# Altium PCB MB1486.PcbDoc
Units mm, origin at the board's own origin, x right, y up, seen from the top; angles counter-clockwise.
Board outline 25 x 31.2 mm, 4 copper layers (Top Layer, Signal Layer 1, Signal Layer 2, Bottom Layer), stack 1.2 mm thick; 31 components, 28 nets, 234 pads, 74 vias.
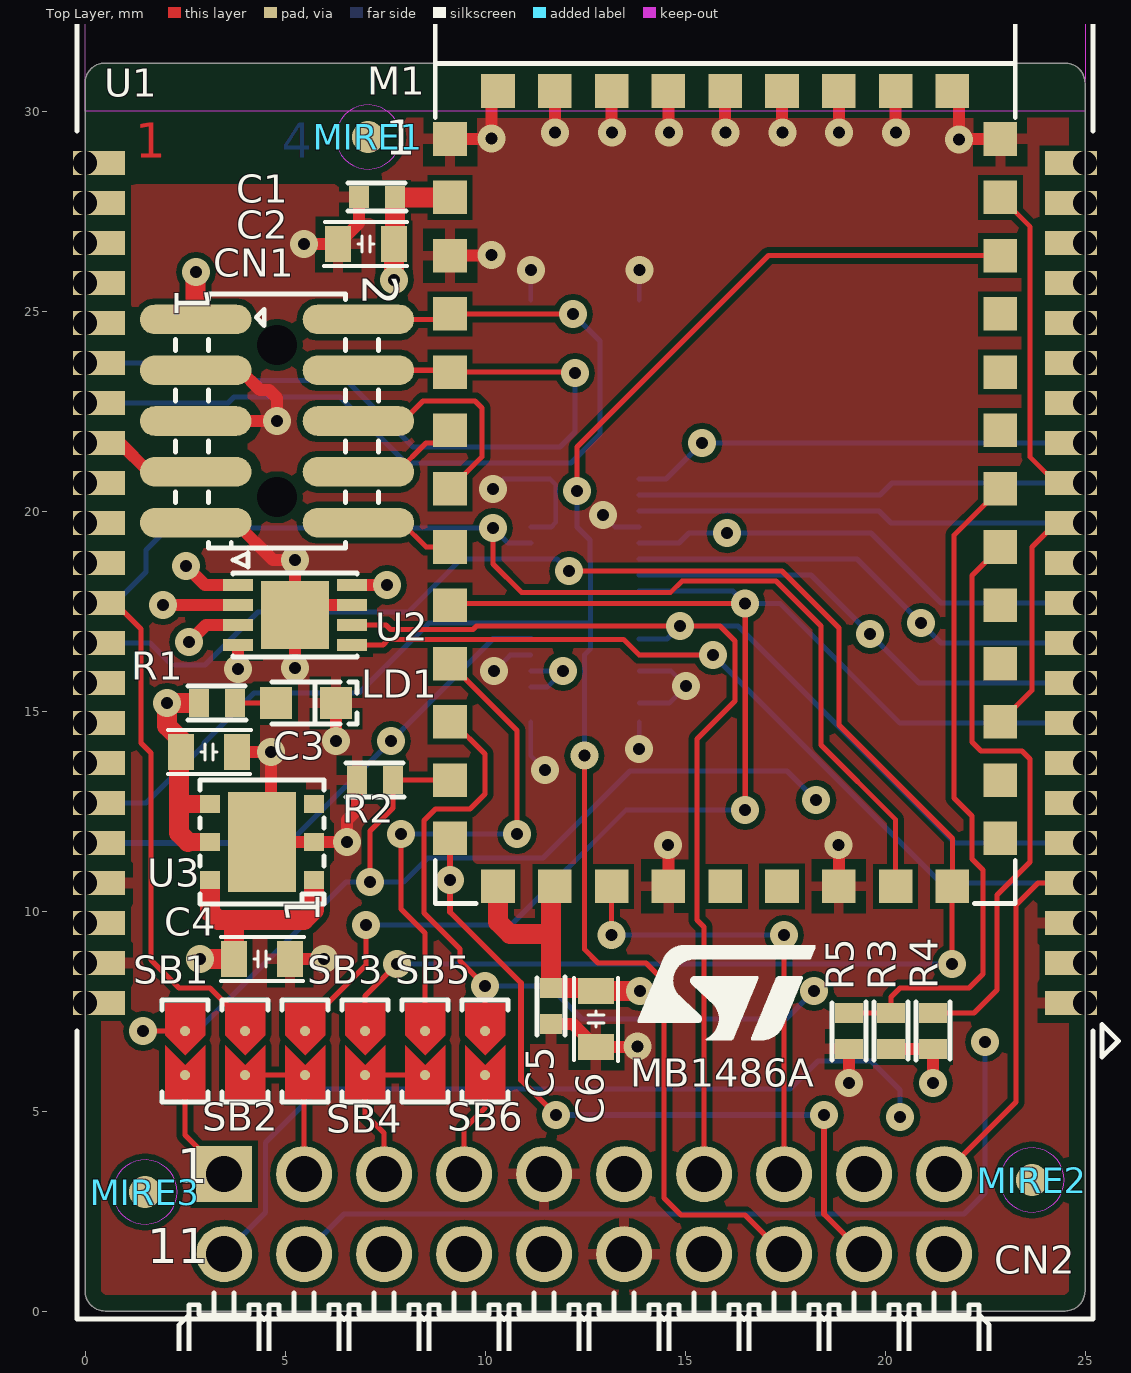
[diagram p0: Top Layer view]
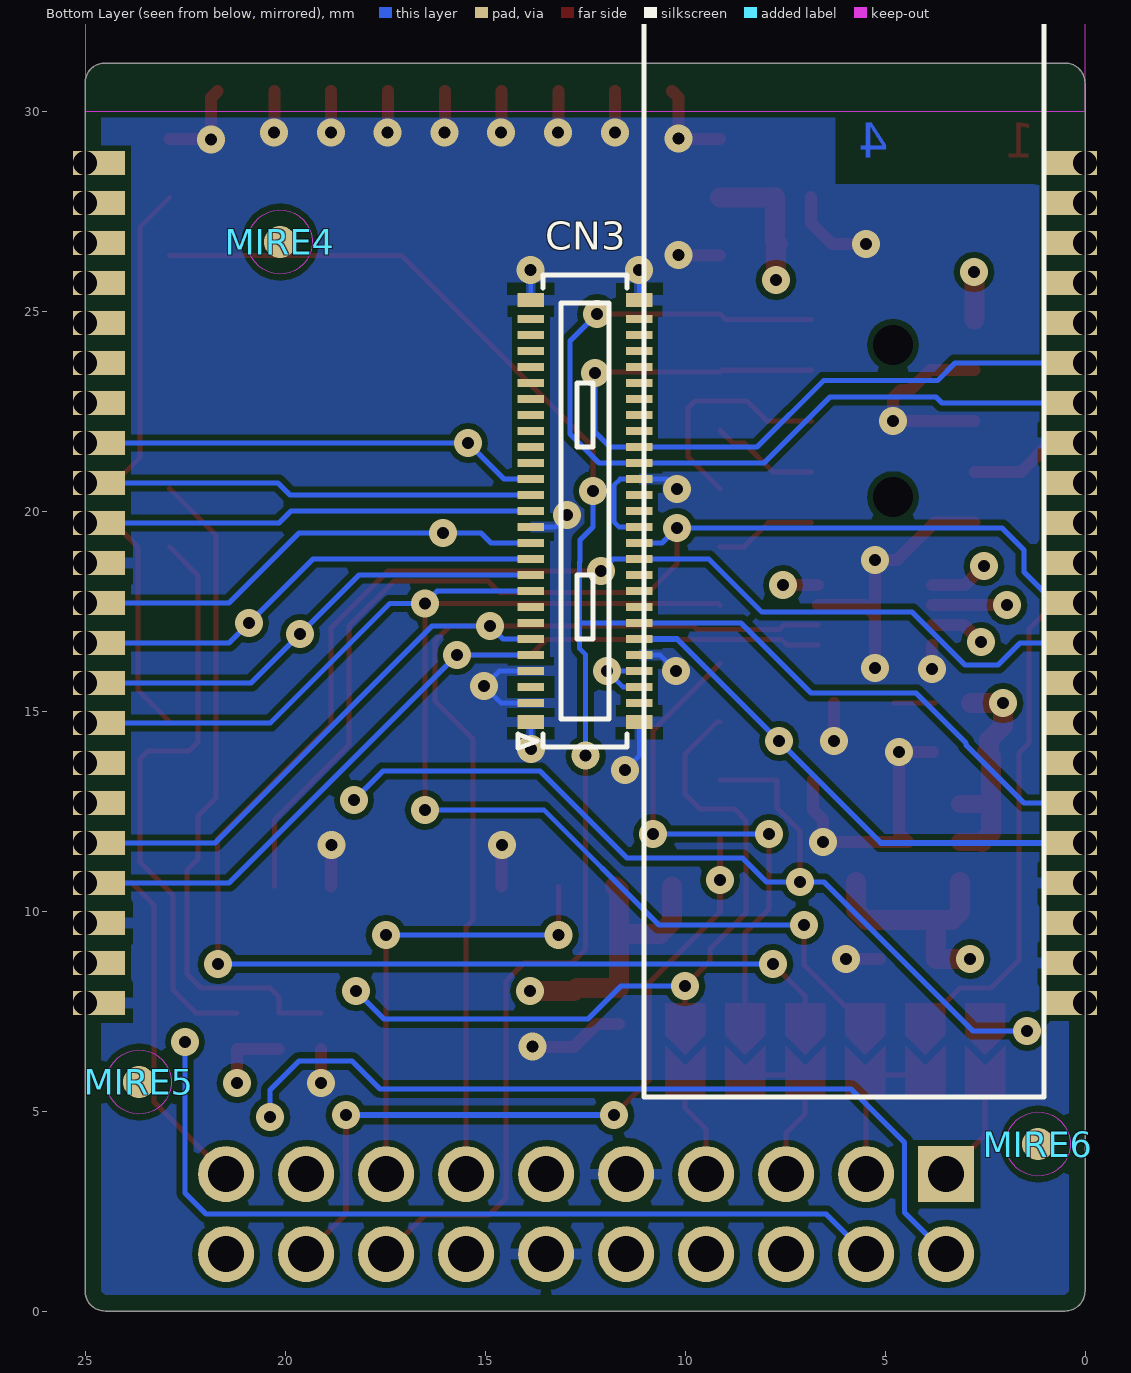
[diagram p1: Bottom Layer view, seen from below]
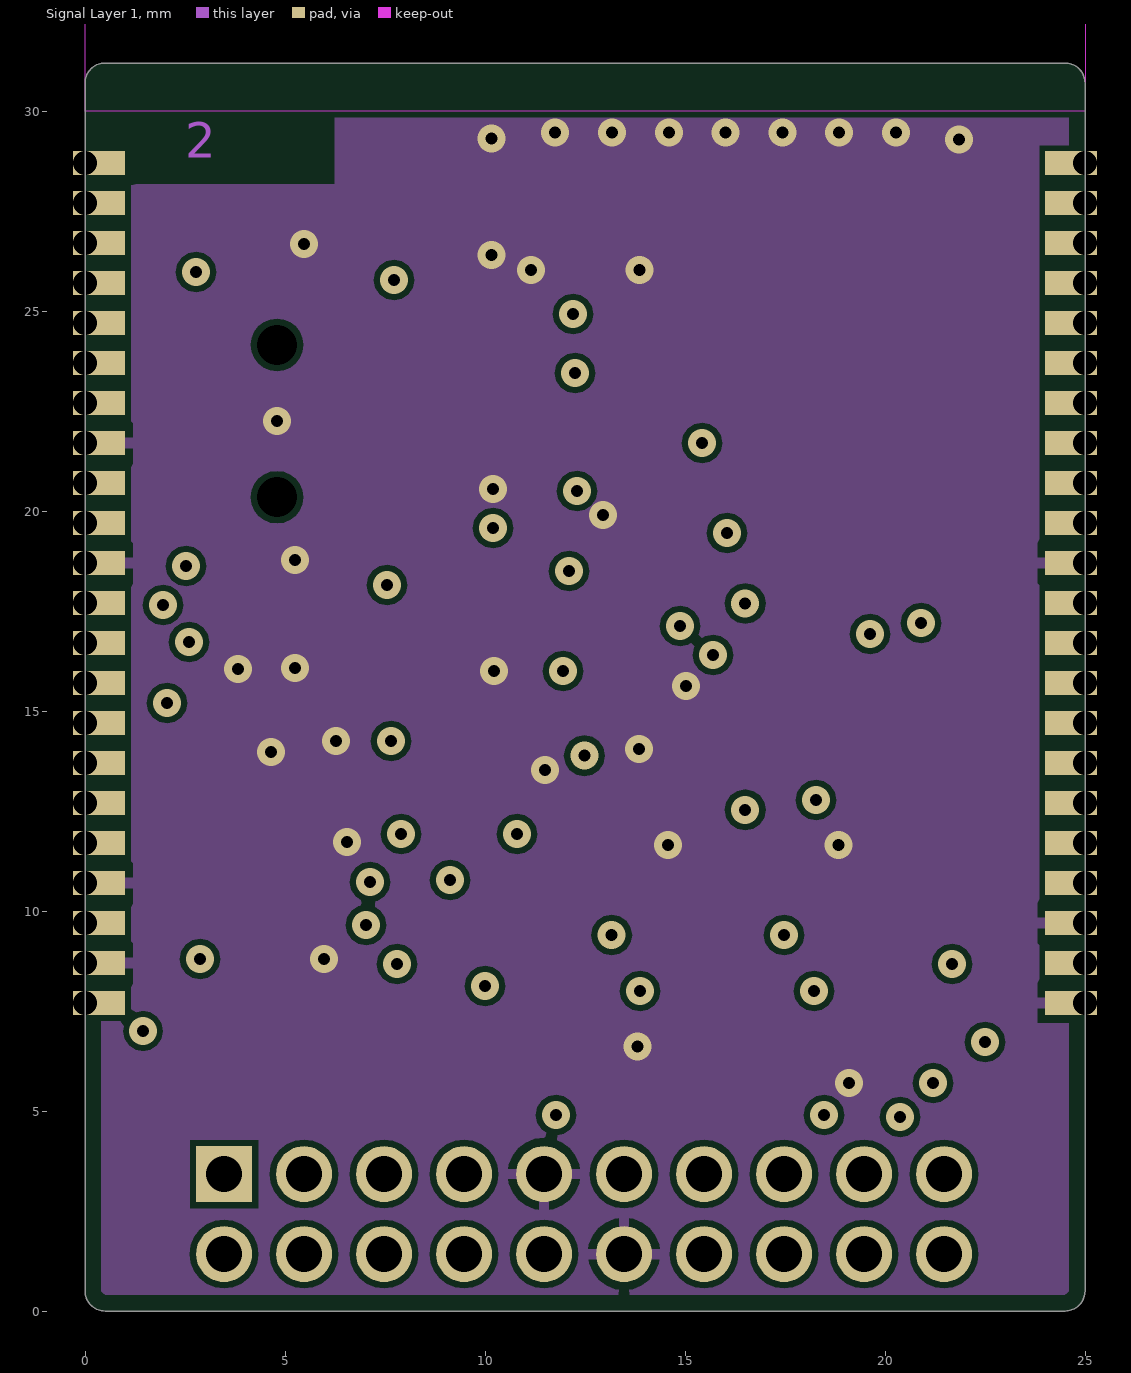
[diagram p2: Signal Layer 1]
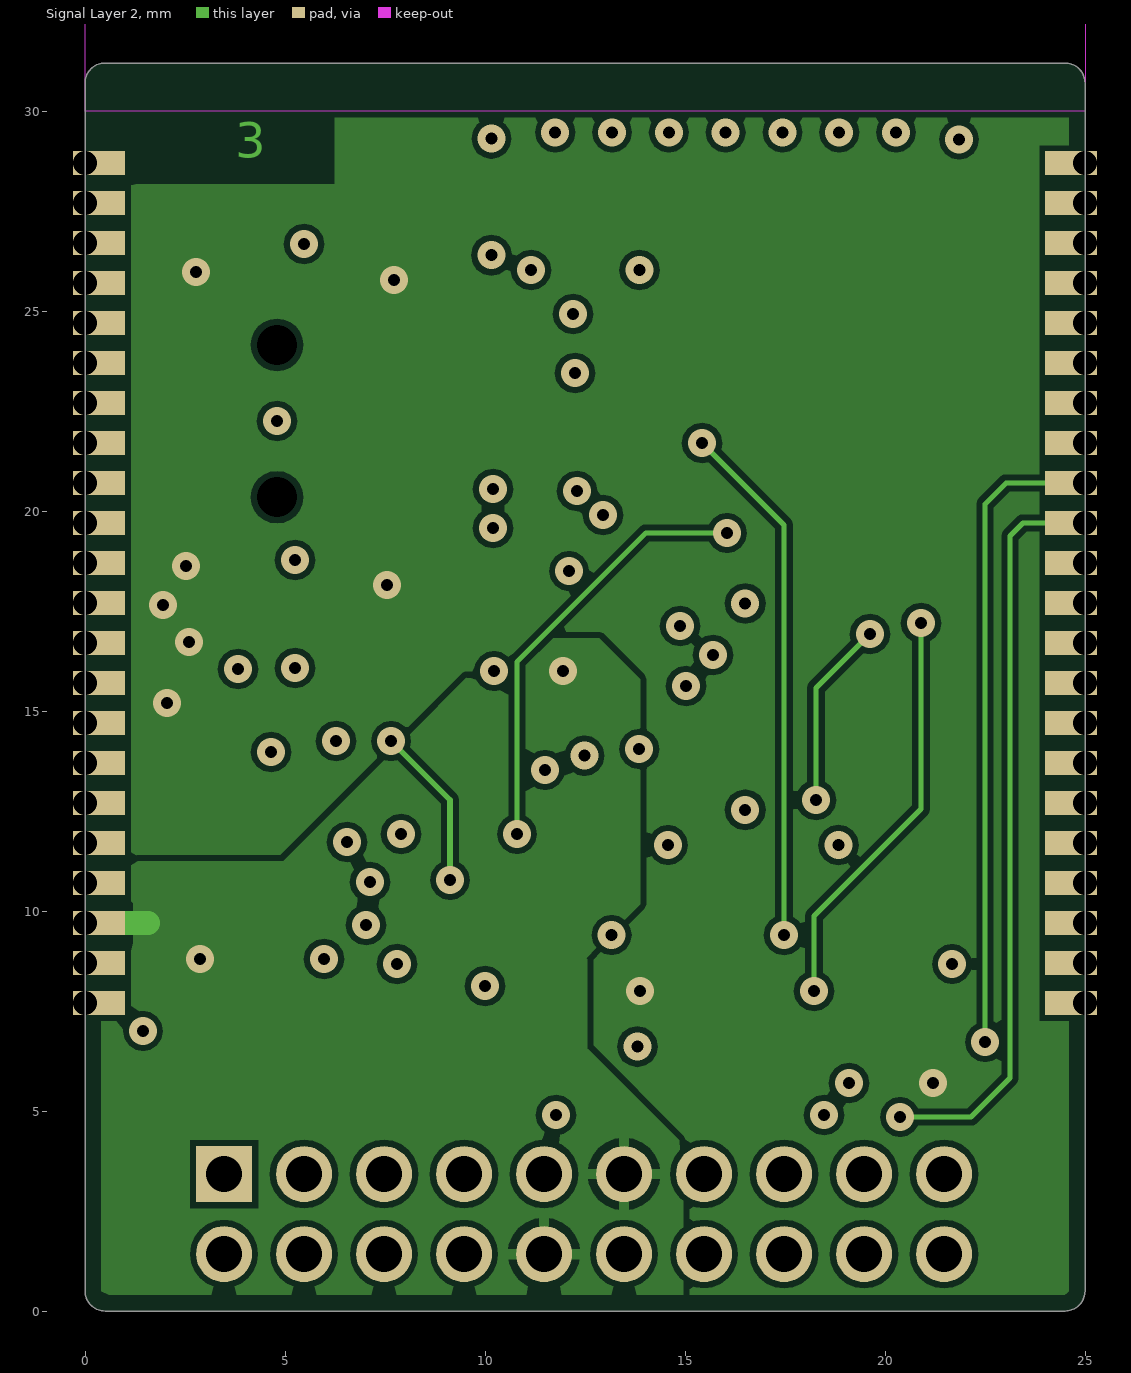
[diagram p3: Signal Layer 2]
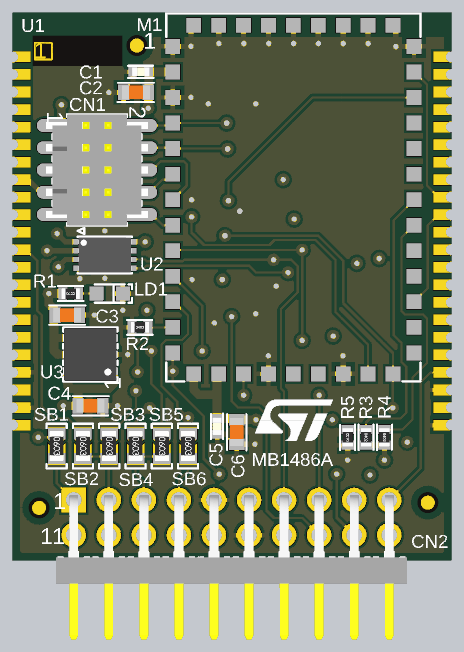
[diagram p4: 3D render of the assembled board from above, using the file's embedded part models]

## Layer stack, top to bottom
Top Solder: solder mask 0.0203, Solder Resist, Dk 3.5
Top Layer: signal copper 0.035
Dielectric 1: core 0.106, FR-4, Dk 4.1
Signal Layer 1: signal copper 0.035
Dielectric 2: prepreg 0.848, Dk 4.25
Signal Layer 2: signal copper 0.035
Dielectric 3: core 0.106, Dk 4.25
Bottom Layer: signal copper 0.035
Bottom Solder: solder mask 0.0203, Solder Resist, Dk 3.5

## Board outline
0,0.5 ccw(c0.5,0.5) 0.5,0 24.5,0 ccw(c24.5,0.5) 25,0.5 25,30.7 ccw(c24.5,30.7) 24.5,31.2 0.5,31.2 ccw(c0.5,30.7) 0,30.7

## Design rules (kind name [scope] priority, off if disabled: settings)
BoardOutlineClearance [All] p1: gap=0.4 ignorepadtopadclearanceinfootprint=FALSE
Clearance Clearance_1 [InNetClass('Iso 250µm')] p1: gap=0.25 ignorepadtopadclearanceinfootprint=FALSE except(0: Arc-Hole Track-Hole SMDPad-Hole THPad-Hole Via-Hole Fill-Hole Poly-Hole Region-Hole Text-Hole)
Clearance [All] p2: gap=0.15 ignorepadtopadclearanceinfootprint=FALSE except(0: Arc-Hole Track-Hole SMDPad-Hole THPad-Hole Via-Hole Fill-Hole Poly-Hole Region-Hole Text-Hole; 0.12: Arc-Arc Arc-Track Arc-SMDPad Arc-Via Arc-Text Track-Track Track-SMDPad Track-Via Track-Text SMDPad-Via SMDPad-Text THPad-Via THPad-Text Via-Via Via-Text Fill-Text Poly-Text Region-Text Text-Text; 0.2: Arc-THPad Track-THPad SMDPad-SMDPad SMDPad-THPad THPad-THPad)
ComponentClearance [All] p1 off: gap=0.025 collisioncheckmode=3 verticalgap=2540 showdistances=TRUE
DiffPairsRouting DiffPairsRouting_USB [InDifferentialPairClass('DIFF_USB')] p1: maxlimit=0.12 minlimit=0.12 mostfreqgap=0.12 toplayer_minwidth=0.13 toplayer_maxwidth=0.13 toplayer_prefwidth=0.13 midlayer1_minwidth=0.13 midlayer1_maxwidth=0.13 midlayer1_prefwidth=0.13 midlayer2_minwidth=0.13 midlayer2_maxwidth=0.13 midlayer2_prefwidth=0.13 bottomlayer_minwidth=0.13 bottomlayer_maxwidth=0.13 bottomlayer_prefwidth=0.13 maxuncoupledlength=12.7
FanoutControl Fanout_Default [All] p1: bgadir=Out bgaviamode=Closest fanoutstyle=Auto fanoutdirection=Alternating viagrid=0.025 // Fanout_Default (Default Rule)
HoleSize [All] p1: absolutevalues=TRUE maxlimit=10 minlimit=0.1 maxpercent=80.000 minpercent=20.000
HoleToHoleClearance [All] p1: gap=0.25 allowstackedmicrovias=TRUE
MatchedLengths "MatchedLengths USB diff" [InDifferentialPairClass('All Differential Pairs')] p1: tolerance=0.5 checknetsindiffpair=TRUE checkdiffpairvsdiffpair=FALSE checkxsignals=FALSE checkothers=FALSE
MinimumSolderMaskSliver [All] p1: minsoldermaskwidth=0
PlaneClearance [All] p1: clearance=0.6
PlaneConnect [All] p1: planeconnectstyle=Relief reliefexpansion=0.508 reliefentries=4 reliefconductorwidth=0.254 reliefairgap=0.2
PolygonConnect PolygonConnect_5V [InNet('5V')] p1: thpad.connectstyle=Relief thpad.reliefconductorwidth=0.254 thpad.reliefentries=4 thpad.polygonreliefangle="90 Angle" thpad.airgapwidth=0.2 smdpad.connectstyle=Relief smdpad.reliefconductorwidth=0.254 smdpad.reliefentries=4 smdpad.polygonreliefangle="90 Angle" smdpad.airgapwidth=0.254 via.connectstyle=Direct via.reliefconductorwidth=0.254 via.reliefentries=4 via.polygonreliefangle="90 Angle" via.airgapwidth=0.254
PolygonConnect [All] p2: thpad.connectstyle=Relief thpad.reliefconductorwidth=0.254 thpad.reliefentries=4 thpad.polygonreliefangle="90 Angle" thpad.airgapwidth=0.2 smdpad.connectstyle=Relief smdpad.reliefconductorwidth=0.254 smdpad.reliefentries=4 smdpad.polygonreliefangle="90 Angle" smdpad.airgapwidth=0.254 via.connectstyle=Direct via.reliefconductorwidth=0.254 via.reliefentries=4 via.polygonreliefangle="45 Angle" via.airgapwidth=0.254
RoutingVias [All] p1: holewidth=0.3 width=0.7 viastyle="Through Hole" minholewidth=0.3 minwidth=0.7 maxholewidth=0.3 maxwidth=0.7
SilkToSilkClearance [All] p1: silktosilkclearance=0
SilkToSolderMaskClearance [IsPad] p1: minsilkscreentomaskgap=0 clearancetoexposedcopper=TRUE
SolderMaskExpansion [All] p1: expansion=0.05
Width Width_OSC [InNetClass('Oscillateur')] p1: maxlimit=0.15 minlimit=0.15 preferedwidth=0.15
Width Width_ALIMS [InNetClass('ALIMS')] p2: maxlimit=10 minlimit=0.12 preferedwidth=0.8 minimp=50.000000 maximp=50.000000 favimp=50.000000
Width Width_GND [InNetClass('GND')] p3: maxlimit=10 minlimit=0.12 preferedwidth=0.3 minimp=50.000000 maximp=50.000000 favimp=50.000000
Width [All] p4: maxlimit=10 minlimit=0.12 preferedwidth=0.127 minimp=50.000000 maximp=50.000000 favimp=50.000000
16 further rules are at their usual default settings.

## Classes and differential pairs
polygon class POLY_DIRECT_ALL: NETC906_2_L01_P192
net class ALIMS: 5V VDD_3V3
net class Oscillateur: DATARDY
net class GND: GND

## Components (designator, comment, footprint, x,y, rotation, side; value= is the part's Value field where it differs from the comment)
C1 "Capacitor" C0402 7.3,27.85 r0 top value=100nF (schematic designator C3)
C2 "Capacitor" C0603 7.025,26.675 r0 top value=2.2uF (schematic designator C4)
C3 "Capacitor" C0603 3.1,13.975 r180 top value=4.7uF (schematic designator C2)
C4 "Capacitor" C0603 4.425,8.8 r180 top value=4.7uF (schematic designator C1)
C5 "Capacitor" C0402 11.65,7.625 r90 top value=100nF
C6 "Capacitor" C0603 12.775,7.3 r90 top value=2.2uF
CN1 "Header 5x2 Generic" CON_SAMTEC_FTSH-105-01-L-DV-K 4.8,22.25 r270 top value=FTSH-105-01-L-DV-K (schematic designator CN4)
CN2 "Header 10x2 STMod+" CON_SAMTEC_TMM-110-01-L-D-RA__STMOD+ 12.475,0.155 r0 top (schematic designator CN3)
CN3 "DF40C-50DP-0.4V(51)" CON_HRS_DF40C-50DP-0.4V_51 12.5,20 r270 bottom (schematic designator CN1)
LD1 "LED_green" LED_0603_VISHAY_VLMTG1300-GS08_GREEN_1A2K_H0P8 5.525,15.2 r0 top value="TRUE GREEN"
M1 "ISM43362-M3G-L44-E" MOD_WIFI_INVENTEK-SYSTEMS_ISM43362-M3G-L44-E-SPI-CXX 16.005,25.19 r90 top value=ISM43362-M3G-L44-E-SPI-Cxx
MIRE1 ".designator" MIRE_PLACE_SMD_0P8MM 7.075,29.35 r0 top
MIRE2 ".designator" MIRE_PLACE_SMD_0P8MM 23.675,3.275 r0 top
MIRE3 ".designator" MIRE_PLACE_SMD_0P8MM 1.5,2.975 r0 top
MIRE4 ".designator" MIRE_PLACE_SMD_0P8MM 20.125,26.725 r180 bottom
MIRE5 ".designator" MIRE_PLACE_SMD_0P8MM 23.65,5.725 r180 bottom
MIRE6 ".designator" MIRE_PLACE_SMD_0P8MM 1.175,4.175 r180 bottom
R1 "Resistor" R0402 3.3,15.2 r0 top value=510R
R2 "Resistor" R0402 7.25,13.275 r0 top value=4K7
R3 "Resistor" R0402 20.15,7 r270 top value=10K (schematic designator R4)
R4 "Resistor" R0402 21.2,7 r270 top value=10K (schematic designator R3)
R5 "Resistor" R0402 19.1,7 r90 top value=10K
SB1 "SB_ON" SOLDER-BRIDGE_R0603-0R 2.5,6.5 r270 top
SB2 "SB_ON" SOLDER-BRIDGE_R0603-0R 4,6.5 r270 top (schematic designator SB4)
SB3 "SB_ON" SOLDER-BRIDGE_R0603-0R 5.5,6.5 r270 top
SB4 "SB_ON" SOLDER-BRIDGE_R0603-0R 7,6.5 r270 top (schematic designator SB5)
SB5 "SB_ON" SOLDER-BRIDGE_R0603-0R 8.5,6.5 r270 top (schematic designator SB6)
SB6 "SB_ON" SOLDER-BRIDGE_R0603-0R 10,6.5 r270 top (schematic designator SB8)
U1 "WIFI MODULE INTERPOSER" CON_MOD2BOARD_WIFI_MURATA_LBEE5PA1LD 12.5,20 r0 top locked value="WIFI INTERPOSER CONNECTOR" (schematic designator U4)
U2 "M24128-DFMC6TP" ICC_DFN8-EPAD_2X3_P050 5.25,17.4 r90 top
U3 "ST1L05CPU33R" ICC_DFN6-EPAD_3X3_P095 4.425,11.725 r90 top value="ST1L05CPU33R 3.3V 1.3A" (schematic designator U1)

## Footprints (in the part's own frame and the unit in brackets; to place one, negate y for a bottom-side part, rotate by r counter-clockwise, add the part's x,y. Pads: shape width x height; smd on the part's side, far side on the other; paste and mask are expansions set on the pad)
C0402 [mm]
  rect 0.51x0.56 smd mask+0.05: 1(-0.45,0) 2(0.45,0)
  silkscreen extent -0.72,-0.35 0.72,0.35, body extent -0.5,-0.3 0.5,0.3, height 0.4
C0603 [mm]
  rect 0.64x0.89 smd mask+0.05: 1(-0.7,0) 2(0.7,0)
  silkscreen extent -1.05,-0.55 1.02,0.55, body extent -0.9,-0.5 0.9,0.5, height 1.4
CON_HRS_DF40C-50DP-0.4V_51 [mm]
  rect 0.2x0.66 smd mask+0.05: 1(4.8,-1.355) 2(4.4,-1.355) 3(4,-1.355) 4(3.6,-1.355) 5(3.2,-1.355) 6(2.8,-1.355) 7(2.4,-1.355) 8(2,-1.355) 9(1.6,-1.355) 10(1.2,-1.355) 11(0.8,-1.355) 12(0.4,-1.355) 13(0,-1.355) 14(-0.4,-1.355) 15(-0.8,-1.355) 16(-1.2,-1.355) 17(-1.6,-1.355) 18(-2,-1.355) 19(-2.4,-1.355) 20(-2.8,-1.355) 21(-3.2,-1.355) 22(-3.6,-1.355) 23(-4,-1.355) 24(-4.4,-1.355) 25(-4.8,-1.355) 26(-4.8,1.355) 27(-4.4,1.355) 28(-4,1.355) 29(-3.6,1.355) 30(-3.2,1.355) 31(-2.8,1.355) 32(-2.4,1.355) 33(-2,1.355) 34(-1.6,1.355) 35(-1.2,1.355) 36(-0.8,1.355) 37(-0.4,1.355) 38(0,1.355) 39(0.4,1.355) 40(0.8,1.355) 41(1.2,1.355) 42(1.6,1.355) 43(2,1.355) 44(2.4,1.355) 45(2.8,1.355) 46(3.2,1.355) 47(3.6,1.355) 48(4,1.355) 49(4.4,1.355) 50(4.8,1.355)
  rect 0.35x0.66 smd mask+0.05: MT1(5.275,-1.355) MT2(-5.275,-1.355) MT3(-5.275,1.355) MT4(5.275,1.355)
  silkscreen extent -5.9,-1.68 5.92,1.05, body extent -5.9,-1.48 5.9,1.49, height 1.3
CON_MOD2BOARD_WIFI_MURATA_LBEE5PA1LD [mm]
  rect 1.3x0.6 hole 0.6 copper offset -0.35,0 paste-10 mask+0.05: 1(12.5,-12.3) 2(12.5,-11.3) 3(12.5,-10.3) 4(12.5,-9.3) 5(12.5,-8.3) 6(12.5,-7.3) 7(12.5,-6.3) 8(12.5,-5.3) 9(12.5,-4.3) 10(12.5,-3.3) 11(12.5,-2.3) 12(12.5,-1.3) 13(12.5,-0.3) 14(12.5,0.7) 15(12.5,1.7) 16(12.5,2.7) 17(12.5,3.7) 18(12.5,4.7) 19(12.5,5.7) 20(12.5,6.7) 21(12.5,7.7) 22(12.5,8.7)
  rect 1.3x0.6 hole 0.6 copper offset 0.35,0 paste-10 mask+0.05: 23(-12.5,8.7) 24(-12.5,7.7) 25(-12.5,6.7) 26(-12.5,5.7) 27(-12.5,4.7) 28(-12.5,3.7) 29(-12.5,2.7) 30(-12.5,1.7) 31(-12.5,0.7) 32(-12.5,-0.3) 33(-12.5,-1.3) 34(-12.5,-2.3) 35(-12.5,-3.3) 36(-12.5,-4.3) 37(-12.5,-5.3) 38(-12.5,-6.3) 39(-12.5,-7.3) 40(-12.5,-8.3) 41(-12.5,-9.3) 42(-12.5,-10.3) 43(-12.5,-11.3) 44(-12.5,-12.3)
  Keep-Out Layer region: -12.5,20 12.5,20 12.5,10 -12.5,10
  silkscreen extent -12.7,-20.2 13.33,20.2
CON_SAMTEC_FTSH-105-01-L-DV-K [mm]
  oval 0.74x2.79 smd mask+0.05: 1(-2.54,-2.035) 2(-2.54,2.035) 3(-1.27,-2.035) 4(-1.27,2.035) 5(0,-2.035) 6(0,2.035) 7(1.27,-2.035) 8(1.27,2.035) 9(2.54,-2.035) 10(2.54,2.035)
  round 0 hole 1 unplated paste-10 mask+0.05: NPTH1(-1.905,0) NPTH2(1.905,0)
  silkscreen extent -3.18,-2.54 3.18,2.54, body extent -3.18,-2.92 3.18,2.92, height 6.12
CON_SAMTEC_TMM-110-01-L-D-RA__STMOD+ [mm]
  rect 1.4x1.4 hole 0.9 mask+0.05: 1(-9,3.27)
  round 1.4 hole 0.9 mask+0.05: 2(-7,3.27) 3(-5,3.27) 4(-3,3.27) 5(-1,3.27) 6(1,3.27) 7(3,3.27) 8(5,3.27) 9(7,3.27) 10(9,3.27) 11(-9,1.27) 12(-7,1.27) 13(-5,1.27) 14(-3,1.27) 15(-1,1.27) 16(1,1.27) 17(3,1.27) 18(5,1.27) 19(7,1.27) 20(9,1.27)
  silkscreen extent -10.12,-4.7 10.13,0.3, body extent -10.15,-6.35 10.15,3.52, height 4
ICC_DFN6-EPAD_3X3_P095 [mm]
  rect 0.45x0.5 smd mask+0.05: 1(-0.95,-1.3) 2(0,-1.3) 3(0.95,-1.3) 4(0.95,1.3) 5(0,1.3) 6(-0.95,1.3)
  rect 2.5x1.7 smd mask+0.05: EP(0,0)
  silkscreen extent -1.55,-1.55 1.55,1.55, body extent -1.55,-1.55 1.55,1.55, height 1
ICC_DFN8-EPAD_2X3_P050 [mm]
  rect 0.3x0.75 smd mask+0.05: 1(0.75,1.425) 2(0.25,1.425) 3(-0.25,1.425) 4(-0.75,1.425) 5(-0.75,-1.425) 6(-0.25,-1.425) 7(0.25,-1.425) 8(0.75,-1.425)
  rect 1.7x1.7 smd mask+0.05: EP(0,0)
  silkscreen extent -1.05,-1.55 1.55,1.55, body extent -1.05,-1.55 1.05,1.55, height 0.9
LED_0603_VISHAY_VLMTG1300-GS08_GREEN_1A2K_H0P8 [mm]
  rect 0.8x0.8 smd mask+0.05: 1(-0.75,0) 2(0.75,0)
  silkscreen extent -0.85,-0.53 1.28,0.53, body extent -0.85,-0.45 0.85,0.45, height 0.8
MIRE_PLACE_SMD_0P8MM [mm]
  round 0.8 smd paste-10 mask+0.2: 1(0,0)
  Top Layer keep-out circle w0.01: c0,0 r0.804
MOD_WIFI_INVENTEK-SYSTEMS_ISM43362-M3G-L44-E-SPI-CXX [mm] "INTEGRATED ANTENNA"
  rect 0.84x0.84 smd mask+0.05: 1(4.11,6.88) 2(2.653,6.88) 3(1.196,6.88) 4(-0.261,6.88) 5(-1.718,6.88) 6(-3.175,6.88) 7(-4.632,6.88) 8(-6.089,6.88) 9(-7.546,6.88) 10(-9.003,6.88) 11(-10.46,6.88) 12(-11.917,6.88) 13(-13.374,6.88) 14(-14.574,5.68) 15(-14.574,4.26) 16(-14.574,2.84) 17(-14.574,1.42) 18(-14.574,0) 19(-14.574,-1.42) 20(-14.574,-2.84) 21(-14.574,-4.26) 22(-14.574,-5.68) 23(-13.374,-6.88) 24(-11.917,-6.88) 25(-10.46,-6.88) 26(-9.003,-6.88) 27(-7.546,-6.88) 28(-6.089,-6.88) 29(-4.632,-6.88) 30(-3.175,-6.88) 31(-1.718,-6.88) 32(-0.261,-6.88) 33(1.196,-6.88) 34(2.653,-6.88) 35(4.11,-6.88) 36(5.31,-5.68) 37(5.31,-4.26) 38(5.31,-2.84) 39(5.31,-1.42) 40(5.31,0) 41(5.31,1.42) 42(5.31,2.84) 43(5.31,4.26) 44(5.31,5.68)
  silkscreen extent -15,-7.25 15,7.25, body extent -15,-7.25 15,7.25, height 2.9
R0402 [mm]
  rect 0.51x0.7 smd mask+0.05: 1(-0.45,0) 2(0.45,0)
  silkscreen extent -0.72,-0.43 0.72,0.43, body extent -0.52,-0.3 0.52,0.3, height 0.4
SOLDER-BRIDGE_R0603-0R [mil]
  round 10 smd paste-393.7: 1(-19.68,0) 2(23.62,0)
  Top Layer region: -5.91,19.68 13.78,0 -5.91,-19.68 47.24,-19.68 47.24,19.68 -5.91,19.68
  Top Layer region: -47.24,-19.68 -47.24,19.68 -15.75,19.68 3.94,0 -15.75,-19.68 -47.24,-19.68
  silkscreen extent -50,-23 50,23, body extent -36,-20 36,20, height 22

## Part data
C1 C5: library part MCD-01123, "Capacitor, MLCC,100nF, 10V, X7R, 10%, 0402, T=0.5mm", Manufacturer=MURATA, Manufacturer_Part_Number=GRM155R71A104KA01, Package=C0402
C2 C6: library part MCD-00012, "Capacitor, MLCC, 2.2uF, 10V, X5R, 10%, 0603, T=0,8mm", Alternate_Manufacturer=KEMET, Alternate_Manufacturer_Part_Number=C0603C225K8PACTU, Manufacturer=YAGEO, Manufacturer_Part_Number=CC0603KRX5R6BB225, Package=C0603
C3 C4: library part MCD-00009, "Capacitor, MLCC, 4.7uF, 16V, X5R, 10%, 0603, T=0.8mm", Manufacturer=YAGEO, Manufacturer_Part_Number=CC0603KRX5R7BB475, Package=C0603
CN1: library part MCD-00610, "Surface mount, vertical male connector. Double row of 5 pins, 1.27mm pitch, 3.05mm lead. Mates with FFSD connector", Manufacturer=SAMTEC, Manufacturer_Part_Number=FTSH-105-01-L-DV-K
CN2: library part MCD-00288, "Header 10x2, 2mm, RA, TH, Height 3.20mm/3.50mm", Manufacturer=SAMTEC, Manufacturer_Part_Number=TMM-110-01-L-D-RA
CN3: library part MCD-01227, "Header 25x2, 0.4mm pitch, VR, SMT, Height 1.5mm", Manufacturer=HIROSE
LD1: library part MCD-00589, "LED Green, 0603 SMD, Fw Voltage = 2.8V - 3.6V", Alternate_Manufacturer="OSRAM OPTO SEMICONDUCTORS", Alternate_Manufacturer_Part_Number="LG Q396-PS-35", Manufacturer=VISHAY, Manufacturer_Part_Number=VLMTG1300-GS08, Package="LED 0603"
M1: library part MCD-00174, "WIFI Module ISM43362-M3G-L44-E: IEEE802.11 b/g/n integrated Antenna", Manufacturer="INVENTEK SYSTEMS", Manufacturer_Part_Number=ISM43362-M3G-L44-E-SPI-C3.5.2.1
R1: library part MCD-00064, "Resistor,510R,0402,1%,1/16W", Manufacturer=YAGEO, Manufacturer_Part_Number=RC0402FR-07510RL, Package=R0402
R2: library part MCD-00065, "Resistor,4K7,0402,1%,1/16W", Alternate_Manufacturer=YAGEO, Alternate_Manufacturer_Part_Number=RT0402FRE074K7L, Manufacturer_Part_Number=RC0402FR-074K7L, Package=R0402
R3 R4 R5: library part MCD-00053, "Resistor,10K,0402,1%,1/16W", Manufacturer=YAGEO, Manufacturer_Part_Number=RC0402FR-0710KL, Package=R0402
SB1 SB2 SB3 SB4 SB5 SB6: library part MCD-00071, "Solder Bridge ON"
U1: library part MCD-01334, "44 pins Generic Interposer Connector (Not Fitted : Footprint only)", Manufacturer=N/A
U2: library part MCD-01213, "I2C Memory 3V3, 128-Kbit, 2x3x0.55mm, UFDFPN8", Manufacturer=STMICROELECTRONICS
U3: library part MCD-01025, "LDO, 3.3V, 1.3A, Very low quiescent current BiCMOS voltage regulator", Manufacturer=STMICROELECTRONICS, Package=DFN6-3x3

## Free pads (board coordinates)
  round 0.508 on Mech16: 1(18.738,-18.015) 1(67.585,-18.015)

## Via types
v1: diameter 0.7, hole 0.3, Top Layer to Bottom Layer, tented both sides, 74 vias

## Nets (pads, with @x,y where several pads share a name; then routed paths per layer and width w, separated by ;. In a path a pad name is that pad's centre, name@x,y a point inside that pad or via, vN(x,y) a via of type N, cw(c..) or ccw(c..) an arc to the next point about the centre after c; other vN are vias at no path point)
5V: C4.2 CN2.6 CN2.15 CN3.48 CN3.49 U1.42 U3.1 U3.6 | length 9.4
  Top Layer w0.5: v1(2.875,8.8) C4.2 3.725,9.775 ; U3.6@3.125,10.725 3.125,9.975 3.325,9.775 3.725,9.775 ; U3.1@5.725,10.725 5.725,10.025 5.475,9.775 3.725,9.775
  Signal Layer 2 w0.6: U1.42 1.575,9.7
  Bottom Layer w0.12: CN3.49 11.55,15.6 v1(11.95,16) CN3.48
BOOT: CN2.18 CN3.45 M1.33 U1.39 | length 51.2
  Top Layer w0.127: v1(12.3,20.5) 12.3,21.6 17.086,26.386 M1.33 ; v1(12.484,13.884) 12.484,9.041 12.825,8.7 14.025,8.7 14.475,8.25 14.475,2.825 14.9,2.4 16.5,2.4 CN2.18
  Bottom Layer w0.127: U1.39 1.525,12.7 2.975,14.15 2.975,14.2 4.225,15.45 6.85,15.45 8.6,17.2 CN3.45 12.634,17.2 ; v1(12.3,20.5) 12.3,19.6 12.625,19.275 12.625,18.738 12.634,18.729 12.634,17.2 ; v1(12.484,13.884) 12.484,16.409 12.634,16.559 12.634,17.2
CFG0: M1.28 R4.1 | length 14.8
  Top Layer w0.127: R4.1 22.225,7.45 22.8,8.025 22.8,10.4 23.625,11.225 23.625,13.8 23.425,14 22.4,14 22.175,14.225 22.175,18.391 M1.28
CFG1: M1.29 R3.1 R5.2 | length 16.9
  Top Layer w0.127: R5.2 R3.1 20.15,7.85 20.375,8.075 22.1,8.075 22.45,8.425 22.45,11.025 22.175,11.3 22.175,12.375 21.725,12.825 21.725,19.398 M1.29
DATARDY: CN2.19 CN3.46 M1.13 U1.40 | length 35.9
  Top Layer w0.15: M1.13 9.125,9.975 10.9,8.2 10.9,5.775 v1(11.775,4.9) ; v1(18.475,4.9) 18.475,2.425 CN2.19
  Signal Layer 2 w0.15: v1(7.65,14.25) 9.125,12.775 v1(9.125,10.775)
  Bottom Layer w0.15: U1.40 5.1,11.7 v1(7.65,14.25) 10.2,16.8 CN3.46 ; v1(11.775,4.9) v1(18.475,4.9)
GND: C1.1 C2.1 C3.1 C4.1 C5.1 C6.1 CN1.3 CN1.5 CN1.7 CN1.9 CN2.5 CN2.16 CN3.1 CN3.3 CN3.12 CN3.36 CN3.39 CN3.47 CN3.MT1 CN3.MT2 CN3.MT3 CN3.MT4 LD1.2 M1.1 M1.3 M1.17 M1.20 M1.35 M1.36 M1.37 M1.38 M1.39 M1.40 M1.41 M1.42 M1.43 M1.44 R2.1 R5.1 U1.1 U1.3 U1.12 U1.30 U1.33 U1.41 U1.43 U2.4 U2.7 U2.EP U3.2 U3.EP | length 56.6
  Top Layer w0.3: U1.30 0.875,21.7 1.595,20.98 CN1.7 ; CN1.9 3.765,19.71 4.7,18.775 v1(5.25,18.775) U2.EP ; CN1.5 v1(4.8,22.25) 4.8,22.825 4.6,23.025 4.375,23.025 3.88,23.52 CN1.3 ; C3.1 v1(4.65,13.975) 4.65,11.95 U3.EP U3.2 v1(6.55,11.725) 6.55,12.275 6.8,12.525 R2.1 ; v1(3.825,16.05) 3.825,16 U2.4 ; C4.1 v1(5.975,8.8) ; v1(5.25,16.075) U2.EP ; v1(5.475,26.675) C2.1 6.85,27.2 C1.1 ; v1(6.275,14.25) LD1.2 ; U2.7 5.5,17.65 U2.EP ; M1.3 v1@10.149,26.386 ; M1.1 v1@10.149,29.3 ; v1(10.159,29.31) 10.159,30.334 M1.44 ; C5.1 12.2,7.175 C6.1 v1@13.799,6.6 ; v1@11.745,29.476 M1.43 ; v1@13.165,29.476 M1.42 ; v1(14.575,11.65) 14.585,11.64 M1.17 ; v1@14.585,29.476 M1.41 ; v1@16.005,29.476 M1.40 ; v1@17.425,29.476 M1.39 ; M1.20 v1@18.845,11.64 ; v1@18.845,29.476 M1.38 ; v1(19.1,5.7) R5.1 ; v1@20.265,29.476 M1.37 ; M1.36 21.851,30.334 v1(21.851,29.29) ; v1@21.861,29.3 M1.35
  Bottom Layer w0.12: v1(10.2,20.55) 10.45,20.8 CN3.36 11.625,20.8 11.77,20.655 11.77,19.72 11.65,19.6 CN3.39 ; v1(10.225,16) 10.625,16.4 CN3.47 ; CN3.MT4 11.145,13.88 v1(11.5,13.525) ; CN3.MT3 11.145,26.02 v1(11.15,26.025) ; v1(12.95,19.9) 13.25,19.6 CN3.12 ; v1@13.85,13.95 13.855,13.955 v1(13.855,14.05) CN3.MT1 ; CN3.1 14.6,15.2 v1(15.025,15.625) 14.65,16 CN3.3 ; CN3.MT2 v1@13.855,26.02
  other v1: 13.809,6.61 18.835,11.65 13.86,26.025 10.159,26.396 11.755,29.466 13.175,29.466 14.595,29.466 16.015,29.466 17.435,29.466 18.855,29.466 20.275,29.466
GPIO2: CN2.11 CN3.13 M1.25 U1.13 | length 56.7
  Top Layer w0.127: M1.25 23.675,15.52 23.675,19.1 24.275,19.7 U1.13
  Signal Layer 2 w0.127: v1(20.375,4.85) 22.15,4.85 23.125,5.825 23.125,19.375 23.45,19.7 U1.13@24.537,19.7
  Bottom Layer w0.127: CN2.11 4.511,2.461 4.511,4.211 5.85,5.55 17.625,5.55 18.325,6.25 19.65,6.25 20.375,5.525 v1(20.375,4.85) ; CN3.13 19.85,20 20.15,19.7 U1.13
I2C_SCL: CN2.7 CN3.5 U1.5 U2.6 | length 37.1
  Top Layer w0.127: U2.6 7.525,17.15 7.635,17.04 9.7,17.04 9.785,17.125 v1(14.875,17.125) 15.875,17.125 16.25,16.75 16.25,15.25 15.3,14.3 15.3,9.775 15.475,9.6 CN2.7
  Bottom Layer w0.127: CN3.5 14.55,16.8 v1(14.875,17.125) 16.325,17.125 21.75,11.7 U1.5
I2C_SDA: CN2.10 CN3.4 U1.4 U2.5 | length 32.2
  Top Layer w0.127: U2.5 7.45,16.65 7.593,16.793 13.461,16.793 13.855,16.4 v1(15.7,16.4) ; CN2.10 23.275,5.225 23.275,10.15 23.825,10.7 U1.4
  Bottom Layer w0.127: CN3.4 v1(15.7,16.4) 21.4,10.7 U1.4
JTCK: CN1.4 CN3.34 M1.5 U1.28 | length 20.2
  Top Layer w0.127: CN1.4 9.077,23.52 M1.5 12.228,23.472 v1(12.25,23.45)
  Bottom Layer w0.127: U1.28 3.25,23.7 3.684,23.266 6.534,23.266 8.2,21.6 CN3.34 11.875,21.6 12.25,21.975 v1(12.25,23.45)
JTDI: CN1.8 M1.6 | length 2.7
  Top Layer w0.127: CN1.8 7.805,20.98 8.525,21.7 8.81,21.7 M1.6
JTDO: CN1.6 M1.7 | length 5.7
  Top Layer w0.127: CN1.6 7.95,22.25 8.45,22.75 9.75,22.75 9.925,22.575 9.925,21.358 M1.7
JTMS: CN1.2 CN3.35 M1.4 U1.29 | length 22.2
  Top Layer w0.127: CN1.2 8.986,24.79 M1.4 9.129,24.925 v1(12.2,24.925)
  Bottom Layer w0.127: U1.29@0.463,22.7 3.575,22.7 3.725,22.85 6.375,22.85 8.025,21.2 CN3.35 12.15,21.2 12.875,21.925 12.875,24.25 v1(12.2,24.925)
JTRST: CN1.10 M1.8 | length 2.5
  Top Layer w0.127: CN1.10 7.92,19.71 8.529,19.101 M1.8
NetCN2_1: CN2.1 SB1.2 | length 2.9
  Top Layer w0.127: SB1.2 2.5,4.4 CN2.1
NetCN2_2: CN2.2 SB2.2 SB3.2 | length 4
  Top Layer w0.127: SB2.2 SB3.2 5.475,5.875 CN2.2
NetCN2_3: CN2.3 SB4.2 SB5.2 | length 4.2
  Top Layer w0.127: CN2.3 7.475,4.45 7,4.925 SB4.2 SB5.2
NetCN2_4: CN2.4 SB6.2 | length 2.7
  Top Layer w0.127: CN2.4 9.475,4.55 10,5.075 SB6.2
NetLD1_1: LD1.1 R1.2 | length 1
  Top Layer w0.127: R1.2 LD1.1
NRST: CN2.12 CN3.14 M1.34 U1.14 | length 56.4
  Top Layer w0.12: M1.34 23.625,27.103 23.625,21.35 24.275,20.7 U1.14@24.54,20.7
  Signal Layer 2 w0.127: v1(22.5,6.725) 22.5,20.173 23.027,20.7 U1.14@24.537,20.7
  Bottom Layer w0.127: CN2.12 6.475,2.425 21.975,2.425 22.5,2.95 v1(22.5,6.725) ; CN3.14 19.875,20.4 20.175,20.7 U1.14
SPI_MISO: CN3.11 M1.10 SB5.1 U1.11 | length 36.2
  Top Layer w0.127: v1(7.9,11.925) 7.9,10.05 8.5,9.45 SB5.1 ; M1.10 10.8,14.512 v1(10.8,11.925)
  Signal Layer 2 w0.127: v1(10.8,11.925) 10.8,16.23 14.02,19.45 v1(16.05,19.45)
  Bottom Layer w0.127: v1(7.9,11.925) v1(10.8,11.925) v1@11,11.725 ; CN3.11 14.85,19.2 15.1,19.45 v1(16.05,19.45) 19.65,19.45 21.4,17.7 U1.11
SPI_MOSI: CN3.8 M1.9 SB3.1 U1.8 | length 39
  Top Layer w0.127: SB3.1 5.5,7.127 7.025,8.652 v1(7.025,9.65) ; M1.9 9.171,17.69 v1(16.505,17.69) v1(16.505,12.53)
  Bottom Layer w0.127: v1(7.025,9.65) 10.65,9.65 13.53,12.53 v1(16.505,12.53) ; CN3.8 16.195,18 v1(16.505,17.69) 17.38,17.69 20.37,14.7 U1.8
SPI_NSS: CN3.9 M1.12 R2.2 SB1.1 U1.9 | length 42.1
  Top Layer w0.127: v1(1.45,7) SB1.1 ; v1(7.125,10.725) 7.125,12 7.7,12.575 R2.2 7.702,13.273 M1.12
  Signal Layer 2 w0.127: v1(18.275,12.775) 18.275,15.575 v1(19.625,16.925)
  Bottom Layer w0.127: v1(1.45,7) 2.8,7 6.525,10.725 v1(7.125,10.725) 7.965,10.725 8.565,11.325 11.45,11.325 13.625,13.5 17.55,13.5 v1(18.275,12.775) ; CN3.9 18.15,18.4 v1(19.625,16.925) 20.85,15.7 U1.9
SPI_SCK: CN3.10 M1.11 SB6.1 U1.10 | length 41.1
  Top Layer w0.127: M1.11 9.195,14.73 10,13.925 10,12.925 9.625,12.55 8.759,12.55 8.475,12.266 8.475,9.95 9.375,9.05 9.375,8.75 v1(10,8.125) SB6.1
  Signal Layer 2 w0.127: v1(18.225,8) 18.225,9.875 20.9,12.55 v1(20.9,17.2)
  Bottom Layer w0.127: v1(10,8.125) 11.6,8.125 12.425,7.3 17.525,7.3 v1(18.225,8) ; CN3.10 19.3,18.8 v1(20.9,17.2) 21.4,16.7 U1.10
UART_RXD: CN3.40 M1.21 SB2.1 U1.34 | length 42.4
  Top Layer w0.127: U1.34@0.463,17.7 0.75,17.7 1.4,17.05 1.4,14.2 1.65,13.95 1.65,8.775 2.35,8.075 3.125,8.075 4,7.2 SB2.1 ; v1(10.2,19.575) 10.2,18.675 10.908,17.966 14.641,17.966 14.928,18.253 17.272,18.253 18.4,17.125 18.4,14.15 20.265,12.285 M1.21
  Bottom Layer w0.127: U1.34 0.75,17.7 1.525,18.475 1.525,19.025 2.075,19.575 v1(10.2,19.575) 10.575,19.2 CN3.40
UART_TXD: CN3.41 M1.22 SB4.1 U1.35 | length 45.9
  Top Layer w0.127: SB4.1 7,7.875 v1(7.8,8.675) ; v1(12.1,18.5) 17.425,18.5 18.85,17.075 18.85,14.65 21.685,11.815 M1.22 21.675,10.606 v1(21.675,8.675)
  Bottom Layer w0.127: U1.35@0.463,16.7 1.625,16.7 2.175,16.15 3,16.15 4.325,17.475 8.08,17.475 9.405,18.8 CN3.41 11.8,18.8 v1(12.1,18.5) ; v1(7.8,8.675) v1(21.675,8.675)
VDD_3V3: C1.2 C2.2 C3.2 C5.2 C6.2 CN1.1 M1.2 M1.14 M1.15 R1.1 R3.2 R4.2 U2.1 U2.2 U2.3 U2.8 U3.4 U3.5 | length 25.3
  Top Layer w0.3: v1(1.95,17.65) U2.2 ; v1(2.525,18.625) 3,18.15 U2.1 ; v1(2.6,16.725) 3.025,17.15 U2.3 ; U2.8 v1(7.55,18.15) ; R3.2 R4.2 v1(21.2,5.7)
  Top Layer w0.45: 2.375,12.675 U3.4 ; 2.575,11.725 U3.5
  Top Layer w0.5: 2.375,12.675 2.35,12.65 ; C3.2 2.4,14.275 2.05,14.625 v1(2.05,15.2) R1.1 ; C3.2@2.45,13.975 2.35,13.875 2.35,12.65 ; 2.575,11.725 2.35,11.95 2.35,12.65 ; CN1.1 2.765,25.965 v1(2.775,25.975) ; C2.2@7.675,26.675 7.75,26.75 C1.2 7.757,27.843 M1.2 ; v1(7.725,25.775) C2.2 ; M1.14 10.325,9.725 10.625,9.425 11.65,9.425 ; M1.15 11.65,10.521 11.65,9.425 ; v1(13.875,8) C6.2 12.7,8.075 C5.2 11.65,9.425
WKUP: CN2.8 CN3.15 M1.16 U1.15 | length 36.2
  Top Layer w0.127: v1(13.165,9.4) M1.16 ; CN2.8 v1(17.475,9.4)
  Signal Layer 2 w0.127: v1(15.425,21.7) 17.475,19.65 v1(17.475,9.4)
  Bottom Layer w0.127: v1(13.165,9.4) v1(17.475,9.4) ; CN3.15 14.525,20.8 v1(15.425,21.7) U1.15
pads on no net: CN1.NPTH1 CN1.NPTH2 CN2.9 CN2.13 CN2.14 CN2.17 CN2.20 CN3.2 CN3.6 CN3.7 CN3.16 CN3.17 CN3.18 CN3.19 CN3.20 CN3.21 CN3.22 CN3.23 CN3.24 CN3.25 CN3.26 CN3.27 CN3.28 CN3.29 CN3.30 CN3.31 CN3.32 CN3.33 CN3.37 CN3.38 CN3.42 CN3.43 CN3.44 CN3.50 M1.18 M1.19 M1.23 M1.24 M1.26 M1.27 M1.30 M1.31 M1.32 MIRE1.1 MIRE2.1 MIRE3.1 MIRE4.1 MIRE5.1 MIRE6.1 U1.2 U1.6 U1.7 U1.16 U1.17 U1.18 U1.19 U1.20 U1.21 U1.22 U1.23 U1.24 U1.25 U1.26 U1.27 U1.31 U1.32 U1.36 U1.37 U1.38 U1.44 U3.3

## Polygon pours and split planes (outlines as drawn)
GND on Signal Layer 1 "GND" (solid, pour order 6): 0,30 25,30 25,0 0,0
5V on Signal Layer 2 "5V" (solid, remove dead copper, pour order 10): -0.9,11.25 4.95,11.25 10.525,16.825 12.85,16.825 13.875,15.8 13.875,10.175 12.525,8.825 12.55,8.8 12.55,6.55 12.575,6.55 14.95,4.175 14.95,-0.525 -0.875,-0.525
VDD_3V3 on Signal Layer 2 "VDD_3V3" (solid, pour order 12): 0,0 25,0 25,30 0,30
GND on Top Layer "GND" (solid, remove dead copper, pour order 8): 0,0 25,0 25,30 0,30
GND on Bottom Layer "GND" (solid, pour order 14): 0,0 25,0 25,30 0,30

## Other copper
Top Layer:
  text "1" at 1.256,28.548 h1.5
  text ".Layer_Name" at 7.068,-11.667 h3
  text ".GTL" at 48.763,-11.667 h3
Signal Layer 1:
  text "2" at 2.506,28.548 h1.5
  text ".Layer_Name" at 7.068,-11.667 h3
  text ".G1" at 48.763,-11.667 h3
Signal Layer 2:
  text "3" at 3.756,28.548 h1.5
  text ".Layer_Name" at 7.068,-11.667 h3
  text ".G2" at 48.763,-11.667 h3
Bottom Layer:
  text "4" at 4.912,28.547 h1.5
  text ".GBL" at 37.56,-11.699 h3
  text ".Layer_Name" at 78.874,-11.699 h3
Multi-Layer:
  pour cut-out: 1.131,29.923 1.131,28.173 6.245,28.173 6.245,29.923

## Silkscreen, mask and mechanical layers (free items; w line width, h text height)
Top Overlay:
  drawing of 1036 lines, arcs and shapes, not listed
  text "MB1486A" at 13.625,5.375 h1.2
  text ".Layer_Name" at 7.068,-11.667 h3
  text ".GTO" at 48.763,-11.667 h3
Bottom Overlay:
  lines w0.12: 1.025,5.35 1.025,32.35 11.025,32.35 11.025,5.35 1.025,5.35
  text ".GBO" at 37.56,-11.699 h3
  text ".Layer_Name" at 78.874,-11.699 h3
Top Paste:
  text ".Layer_Name" at 7.068,-11.667 h3
  text ".GTP" at 48.763,-11.667 h3
Bottom Paste:
  text ".GBP" at 37.56,-11.699 h3
  text ".Layer_Name" at 78.874,-11.699 h3
Top Solder:
  region: 1.131,29.923 1.131,28.173 6.245,28.173 6.245,29.923
  text ".Layer_Name" at 7.068,-11.667 h3
  text ".GTS" at 48.763,-11.667 h3
Bottom Solder:
  region: 1.131,29.923 1.131,28.173 6.245,28.173 6.245,29.923
  text ".GBS" at 37.56,-11.699 h3
  text ".Layer_Name" at 78.874,-11.699 h3
M1-Board Shape:
  the board outline again, w0.1
M2-Board Dimensions:
  text ".Layer_Name" at 7.068,-11.667 h3
  text ".GM2" at 48.763,-11.667 h3
M14-Top Assembly:
  text ".Layer_Name" at 7.068,-11.667 h3
  text ".GM14" at 48.763,-11.667 h3
M15-Bottom Assembly:
  text ".GM15" at 37.56,-11.699 h3
  text ".Layer_Name" at 78.874,-11.699 h3
Drill Drawing:
  drawing of 339 lines, arcs and shapes, not listed
  text "PCB SPECIFICATIONS :" at 60.175,83.9 h3
  text "A.   MATERIAL :" at 60.175,79.9 h3
  text "FR-4" at 98.675,79.9 h3
  text "X  TG-170" at 115.175,79.9 h3
  text "TG-150" at 133.425,79.9 h3
  text "TG-140" at 149.425,79.9 h3
  text "B.   MATERIAL FAMILY :" at 60.175,76.9 h3
  text "N/A" at 98.675,76.9 h3
  text "C.   SOLDERMASK COLOR :" at 60.175,73.9 h3
  text "X  GREEN" at 98.675,73.9 h3
  text "BLUE" at 115.175,73.9 h3
  text "RED" at 133.425,73.9 h3
  text "BLACK" at 149.425,73.9 h3
  text "D.   SILKSCREEN COLOR :" at 60.175,70.9 h3
  text "X  WHITE" at 98.675,70.9 h3
  text "YELLOW" at 115.175,70.9 h3
  text "BLACK" at 133.425,70.9 h3
  text "E.   SURFACE FINISH :" at 60.175,67.9 h3
  text "X  ENIG" at 98.675,67.9 h3
  text "IMMERSION SILVER" at 115.175,67.9 h3
  text "IMMERSION TIN" at 149.425,67.9 h3
  text "HASL" at 98.675,64.9 h3
  text "HASL (PB-FREE)" at 115.175,64.9 h3
  text "GOLDEN FINGER" at 149.425,64.9 h3
  text "F.   IMPEDANCE CONTROL :" at 60.175,61.9 h3
  text "NO" at 98.675,61.9 h3
  text "X  YES  (SEE IMPEDANCE TABLE FOR DETAIL INFORMATION)" at 115.175,61.9 h3
  text "G.   THROUGH VIA :" at 60.175,58.9 h3
  text "PLUG THE VIAS WHICH ARE COVERED WITH SOLDERMASK ONE OR TWO SIDE." at 98.675,58.9 h3
  text "PLUG MATERIAL :" at 98.675,55.9 h3
  text "X  SOLDERMASK" at 124.175,55.9 h3
  text "NON-CONDUCTIVE EPOXY." at 149.425,55.9 h3
  text "H.   STACK-UP :" at 60.175,52.9 h3
  text "SEE LAYER STACK-UP SEQUENCE FOR OVERALL THICKNESS." at 98.675,52.9 h3
  text "Layer" at 61.304,43.775 h2
  text "Name" at 69.678,43.775 h2
  text "Material" at 85.875,43.775 h2
  text "Thickness" at 100.429,43.775 h2
  text "Constant" at 112.384,43.775 h2
  text "Board Layer Stack" at 123.448,43.775 h2
  text "MINIMUN PARAMETERS" at 145.25,41.5 h3
  text "1" at 61.304,39.775 h2
  text "Top Overlay" at 69.678,39.775 h2
  text "DEFAULT" at 145.25,36 h3
  text "2" at 61.304,35.775 h2
  text "Top Solder" at 69.678,35.775 h2
  text "Solder Resist" at 85.875,35.775 h2
  text "0,80mil" at 100.429,35.775 h2
  text "3,5" at 112.384,35.775 h2
  text "3" at 61.304,31.775 h2
  text "Top Layer" at 69.678,31.775 h2
  text "Copper" at 85.875,31.775 h2
  text "1,38mil" at 100.429,31.775 h2
  text "TRACKS : 0.120mm           / GAPS : 0.120mm" at 145.25,30.25 h3
  text "4" at 61.304,27.775 h2
  text "Dielectric 1" at 69.678,27.775 h2
  text "FR-4" at 85.875,27.775 h2
  text "4,17mil" at 100.429,27.775 h2
  text "4,1" at 112.384,27.775 h2
  text "5" at 61.304,23.775 h2
  text "Signal Layer 1" at 69.678,23.775 h2
  text "Copper" at 85.875,23.775 h2
  text "1,38mil" at 100.429,23.775 h2
  text "6" at 61.304,19.775 h2
  text "Dielectric 2" at 69.678,19.775 h2
  text "33,39mil" at 100.429,19.775 h2
  text "4,25" at 112.384,19.775 h2
  text "7" at 61.304,15.775 h2
  text "Signal Layer 2" at 69.678,15.775 h2
  text "Copper" at 85.875,15.775 h2
  text "1,38mil" at 100.429,15.775 h2
  text "8" at 61.304,11.775 h2
  text "Dielectric 3" at 69.678,11.775 h2
  text "4,17mil" at 100.429,11.775 h2
  text "4,25" at 112.384,11.775 h2
  text "9" at 61.304,7.775 h2
  text "Bottom Layer" at 69.678,7.775 h2
  text "Copper" at 85.875,7.775 h2
  text "1,38mil" at 100.429,7.775 h2
  text "10" at 61.304,3.775 h2
  text "Bottom Solder" at 69.678,3.775 h2
  text "Solder Resist" at 85.875,3.775 h2
  text "0,80mil" at 100.429,3.775 h2
  text "3,5" at 112.384,3.775 h2
  text "11" at 61.304,-0.225 h2
  text "Bottom Overlay" at 69.678,-0.225 h2
  text ".Layer_Name" at 7.068,-11.667 h3
  text ".DRL" at 48.763,-11.667 h3
  text "Symbol" at 61.381,-29 h2.72
  text "Count" at 72.047,-29 h2.72
  text "Hole Size" at 82.978,-29 h2.72
  text "Plated" at 103.711,-29 h2.72
  text "Hole Type" at 113.075,-29 h2.72
  text "Drill Layer Pair" at 126.707,-29 h2.72
  text "Via/Pad" at 152.549,-29 h2.72
  text "Hole Length" at 163.72,-29 h2.72
  text "Routed Path Length" at 179.319,-29 h2.72
  text "74" at 72.047,-33.7 h2.27
  text "0,300mm (11,81mil)" at 82.978,-33.7 h2.27
  text "PTH" at 103.711,-33.7 h2.27
  text "Round" at 113.075,-33.7 h2.27
  text "Top Layer - Bottom Layer" at 126.707,-33.7 h2.27
  text "Via" at 152.549,-33.7 h2.27
  text "-" at 163.72,-33.7 h2.27
  text "-" at 179.319,-33.7 h2.27
  text "44" at 72.047,-38.4 h2.27
  text "0,600mm (23,62mil)" at 82.978,-38.4 h2.27
  text "PTH" at 103.711,-38.4 h2.27
  text "Round" at 113.075,-38.4 h2.27
  text "Top Layer - Bottom Layer" at 126.707,-38.4 h2.27
  text "Pad" at 152.549,-38.4 h2.27
  text "-" at 163.72,-38.4 h2.27
  text "-" at 179.319,-38.4 h2.27
  text "20" at 72.047,-43.1 h2.27
  text "0,900mm (35,43mil)" at 82.978,-43.1 h2.27
  text "PTH" at 103.711,-43.1 h2.27
  text "Round" at 113.075,-43.1 h2.27
  text "Top Layer - Bottom Layer" at 126.707,-43.1 h2.27
  text "Pad" at 152.549,-43.1 h2.27
  text "-" at 163.72,-43.1 h2.27
  text "-" at 179.319,-43.1 h2.27
  text "2" at 72.047,-47.8 h2.27
  text "1,000mm (39,37mil)" at 82.978,-47.8 h2.27
  text "NPTH" at 103.711,-47.8 h2.27
  text "Round" at 113.075,-47.8 h2.27
  text "Top Layer - Bottom Layer" at 126.707,-47.8 h2.27
  text "Pad" at 152.549,-47.8 h2.27
  text "-" at 163.72,-47.8 h2.27
  text "-" at 179.319,-47.8 h2.27
  text "140 Total" at 72.047,-52.5 h2.27
M20-Top Sheet Box:
  circle w0.254: c85.072,-18.388 r1.3
  region: 84.598,-11.151 69.07,-11.151 68.376,-12.927 67.165,-14.152 65.768,-12.292 65.768,-10.641 66.911,-9.244 68.347,-8.865 84.598,-8.865
  region: 70.594,-19.481 59.838,-19.481 60.832,-16.988 68.689,-16.988 69.138,-16.229 71.347,-18.777
  lines w0.254: 60.832,-16.988 69.624,-16.988 66.557,-13.45 cw(c68.361,-11.506) 68.601,-8.865 85.365,-8.865 84.603,-11.151 ; 64.145,-8.618 cw(c66.572,-9.589) 66.808,-6.986 ; 64.185,-8.586 59.838,-19.481 79.161,-19.481 ccw(c79.41,-16.746) 81.959,-17.766 ; 65.924,-12.52 71.347,-18.777 ; 66.178,-12.52 71.483,-18.642 ; 66.178,-12.266 71.483,-18.388 ; 66.276,-11.151 79.269,-11.151 ; 66.305,-12.139 71.61,-18.261 ; 66.432,-12.012 71.737,-18.134 ; 66.559,-11.885 71.864,-18.007 ; 66.686,-11.758 71.991,-17.88 ; 66.741,-9.806 72.046,-15.927 ; 66.809,-6.986 86.259,-6.986 81.96,-17.764 ; 66.813,-11.631 72.064,-17.69 ; 66.813,-11.377 72.118,-17.499 ; 66.813,-11.123 72.118,-17.245 ; 66.813,-10.234 72.118,-16.356 ; 66.94,-10.996 72.245,-17.118 ; 66.94,-10.615 72.245,-16.737 ; 68.312,-17.001 ccw(c68.417,-16.466) 68.715,-16.009 ; 69.399,-11.138 ccw(c69.373,-11.705) 69.042,-12.167 71.407,-14.896 cw(c69.603,-16.84) 70.336,-19.389 ; 75.68,-19.277 78.569,-10.897 ; 75.902,-19.227 78.771,-10.906 ; 76.029,-19.227 78.898,-10.906 ; 76.283,-19.227 79.152,-10.906 ; 76.537,-19.227 79.406,-10.906 ; 76.791,-19.227 79.66,-10.906 ; 77.045,-19.227 79.914,-10.906 ; 77.299,-19.227 80.168,-10.906 ; 77.553,-19.227 80.422,-10.906 ; 77.807,-19.227 80.676,-10.906 ; 78.016,-19.277 80.905,-10.897 ; 80.905,-11.151 84.598,-11.151 ; 83.929,-11.149 84.691,-8.863 ; 84.095,-11.151 84.857,-8.865 ; 84.349,-11.151 85.111,-8.865
  lines w0.3: -1.932,-23.367 88.068,-23.367 88.068,-3.367 -1.932,-3.367 ; -1.932,-18.367 58.068,-18.367 ; -1.932,-13.367 58.068,-13.367 ; -1.932,-8.367 58.068,-8.367 ; -1.932,-23.367 -1.932,-3.367 ; 38.068,-23.367 38.068,-8.367 ; 58.068,-23.367 58.068,-3.367 ; 75.68,-19.277 78.016,-19.277
  text "Project: '.Board_Name'" at -0.932,-6.583 h3
  text "Layer:" at -0.932,-11.667 h3
  text "Gerber:" at 39.057,-11.667 h3
  text "Variant: '.VariantName'" at -0.932,-16.667 h3
  text "Ref: MB1486" at 39.184,-16.667 h3
  text "R" at 84.564,-19.15 h1.52
  text "Date: 18-APRIL-26" at -0.932,-21.667 h3
  text "Rev: '.Board_PCB_Revision'" at 39.127,-21.667 h3
M21-Bottom Sheet Box:
  circle w0.254: c1.251,-18.388 r1.3
  region: 15.729,-19.481 26.485,-19.481 25.492,-16.988 17.634,-16.988 17.185,-16.229 14.977,-18.777
  region: 1.726,-11.151 17.253,-11.151 17.947,-12.927 19.158,-14.152 20.555,-12.292 20.555,-10.641 19.412,-9.244 17.976,-8.865 1.726,-8.865
  lines w0.254: 1.212,-8.865 1.974,-11.151 ; 1.466,-8.865 2.228,-11.151 ; 1.632,-8.863 2.394,-11.149 ; 1.72,-11.151 0.958,-8.865 17.722,-8.865 cw(c17.962,-11.506) 19.766,-13.45 16.7,-16.988 25.492,-16.988 ; 1.726,-11.151 5.418,-11.151 ; 4.363,-17.764 0.064,-6.986 19.514,-6.986 ; 4.364,-17.766 ccw(c6.914,-16.746) 7.162,-19.481 26.485,-19.481 22.139,-8.586 ; 5.418,-10.897 8.307,-19.277 ; 5.647,-10.906 8.516,-19.227 ; 5.901,-10.906 8.77,-19.227 ; 6.155,-10.906 9.024,-19.227 ; 6.409,-10.906 9.278,-19.227 ; 6.663,-10.906 9.532,-19.227 ; 6.917,-10.906 9.786,-19.227 ; 7.054,-11.151 20.047,-11.151 ; 7.171,-10.906 10.04,-19.227 ; 7.425,-10.906 10.294,-19.227 ; 7.552,-10.906 10.421,-19.227 ; 7.754,-10.897 10.643,-19.277 ; 14.078,-17.118 19.383,-10.996 ; 14.078,-16.737 19.383,-10.615 ; 14.205,-17.499 19.51,-11.377 ; 14.205,-17.245 19.51,-11.123 ; 14.205,-16.356 19.51,-10.234 ; 14.259,-17.69 19.51,-11.631 ; 14.277,-15.927 19.582,-9.806 ; 14.332,-17.88 19.637,-11.758 ; 14.459,-18.007 19.764,-11.885 ; 14.586,-18.134 19.891,-12.012 ; 14.713,-18.261 20.018,-12.139 ; 14.84,-18.642 20.145,-12.52 ; 14.84,-18.388 20.145,-12.266 ; 14.977,-18.777 20.399,-12.52 ; 15.987,-19.389 cw(c16.72,-16.84) 14.916,-14.896 17.281,-12.167 ccw(c16.951,-11.705) 16.925,-11.138 ; 17.608,-16.009 ccw(c17.906,-16.466) 18.011,-17.001 ; 19.515,-6.986 cw(c19.752,-9.589) 22.178,-8.618
  lines w0.3: 8.307,-19.277 10.643,-19.277 ; 28.068,-23.367 28.068,-3.367 ; 28.068,-18.367 88.068,-18.367 ; 28.068,-13.367 88.068,-13.367 ; 28.068,-8.367 88.068,-8.367 ; 48.068,-23.367 48.068,-8.367 ; -1.932,-23.367 88.068,-23.367 88.068,-3.367 -1.932,-3.367 -1.932,-23.367
  text "Project: '.Board_Name'" at 86.874,-6.583 h3
  text "Gerber:" at 46.885,-11.667 h3
  text "Layer:" at 86.874,-11.667 h3
  text "Ref: MB1486" at 46.885,-16.667 h3
  text "Variant: '.VariantName'" at 86.874,-16.667 h3
  text "R" at 1.759,-19.15 h1.52
  text "Rev: '.Board_PCB_Revision'" at 46.942,-21.667 h3
  text "Date: 18-APRIL-26" at 86.874,-21.667 h3

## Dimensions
0.5,0 to 0.5,31.2 on M2-Board Dimensions
0,30.7 to 25,30.7 on M2-Board Dimensions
